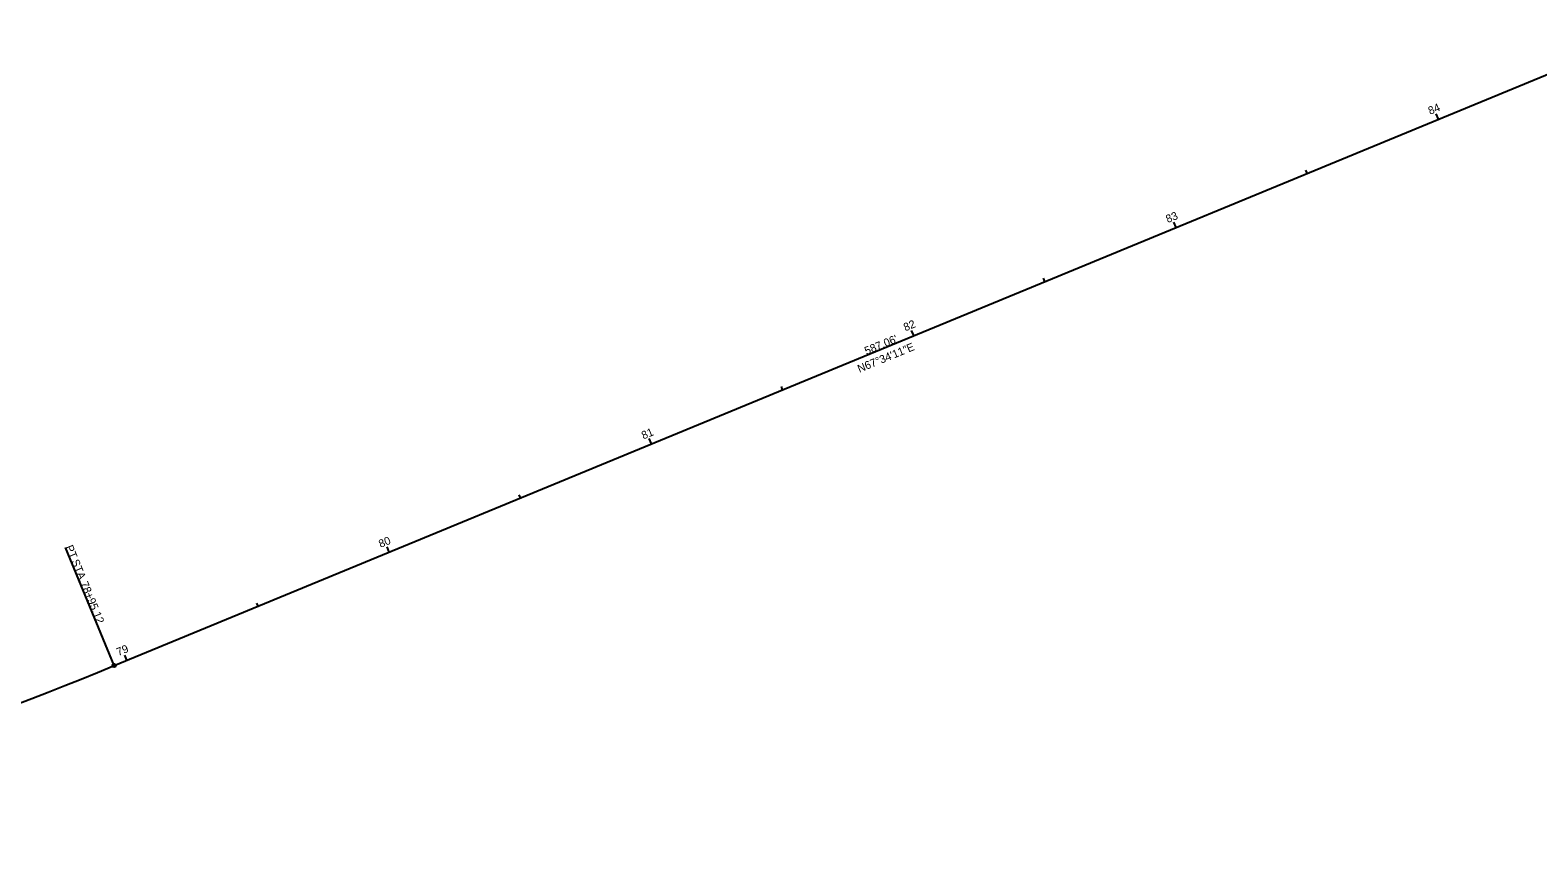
# Model space of a CAD drawing. Extents: x 2202679 to 2204820, y 634848 to 638099.
# Drawn here: x 2203747 to 2204278, y 634871 to 635158 of the extents above; entities that cross this region are included whole.
import ezdxf

# ---------------------------------------------------------------- set-up
doc = ezdxf.new("R2010")
doc.units = 0
for name, color, linetype in [('RW_X_CL', 7, 'Continuous'), ('RW_X_CL_100_Bearings', 7, 'Continuous'), ('RW_X_CL_100_Cardinal_Points', 7, 'Continuous'), ('SC_Scratch1', 7, 'Continuous'), ('SH_Border', 7, 'Continuous')]:
    doc.layers.add(name, color=color, linetype=linetype)

msp = doc.modelspace()

# ---------------------------------------------------------------- linework, layer by layer
at = {"layer": 'RW_X_CL'}
msp.add_line((2203776.43, 634933.8), (2203759.26, 634975.39), dxfattribs=at)
msp.add_circle((2203776.43, 634933.8), 0.6, dxfattribs=at)
at = {"layer": 'RW_X_CL_100_Cardinal_Points'}
for p, q in [((2204243.11, 635126.43), (2204242.35, 635128.28)), ((2204196.89, 635107.36), (2204196.44, 635108.47)), ((2204150.68, 635088.28), (2204149.91, 635090.13)), ((2204104.46, 635069.2), (2204104, 635070.31)), ((2204058.24, 635050.12), (2204057.48, 635051.97)), ((2204012.02, 635031.05), (2204011.57, 635032.15)), ((2203965.81, 635011.97), (2203965.04, 635013.82)), ((2203919.59, 634992.89), (2203919.13, 634994)), ((2203873.37, 634973.81), (2203872.61, 634975.66)), ((2203827.16, 634954.73), (2203826.7, 634955.84)), ((2203780.94, 634935.66), (2203780.17, 634937.5))]:
    msp.add_line(p, q, dxfattribs=at)
at = {"layer": 'SC_Scratch1'}
msp.add_line((2203776.43, 634933.8), (2204319.08, 635157.79), dxfattribs=at)
msp.add_line((2203776.43, 634933.8), (2204319.08, 635157.79), dxfattribs=at)
msp.add_arc((2203229.89, 636257.82), 1432.39, 284.43016, 292.43016, dxfattribs=at)
msp.add_arc((2203229.89, 636257.82), 1432.39, 284.43016, 292.43016, dxfattribs=at)

# ---------------------------------------------------------------- texts
at = {"layer": 'RW_X_CL'}
for s, p in [('PT', (2203759.21, 634975.61)), (' STA. ', (2203760.9, 634971.53)), ('78+95.12', (2203764.51, 634962.79))]:
    msp.add_text(s, height=2.8, rotation=292.4302, dxfattribs=at).set_placement(p)
at = {"layer": 'RW_X_CL_100_Bearings'}
msp.add_text("587.06'", height=2.8, rotation=22.4302, dxfattribs=at).set_placement((2204041.56, 635043.28))
at = {"layer": 'RW_X_CL_100_Cardinal_Points'}
for s, p in [('84', (2204240.16, 635127.92)), ('83', (2204147.73, 635089.77)), ('82', (2204055.29, 635051.61)), ('81', (2203962.97, 635013.5)), ('80', (2203870.36, 634975.27)), ('79', (2203777.95, 634937.13))]:
    msp.add_text(s, height=2.8, rotation=22.4302, dxfattribs=at).set_placement(p)
at = {"layer": 'SH_Border'}
msp.add_text('N67°34\'11"E', height=2.8, rotation=22.4302, dxfattribs=at).set_placement((2204039.08, 635037.02))

doc.saveas('drawing.dxf')
